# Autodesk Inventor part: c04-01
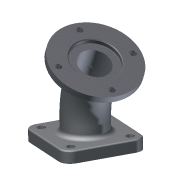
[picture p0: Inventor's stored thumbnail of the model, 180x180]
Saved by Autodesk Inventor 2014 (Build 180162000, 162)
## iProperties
Created: 2010-11
Part Number: c04-01
Material: Generic
Document SubType Name: Modeling
Designer: Thom Tremblay
Density: 1 g/cm^3
Appearance: Aluminum Cast
Author: Thom Tremblay
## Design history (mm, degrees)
sketch "Sketch1"
  geometry: L1 (50, 50)-(50, -50); L2 (50, -50)-(-50, -50); L3 (-50, -50)-(-50, 50); L4 (-50, 50)-(50, 50); C1 r 28 at (0, 0); C2 r 20 at (0, 0); 2 further points
  constraints: 8 end point, 3 coincident, 2 centre point, 1 horizontal, 9 other
  dimensions: "d0" = 100 distance of L3.end L1.start; "d8" = 8 radial gap between concentric circles of C1 C2; "d17" = 40 diameter of C2
extrude "Extrusion1" new body sketch "Sketch1" distance "d1" = 15; taper "d2" = 0 deg
sketch "Sketch2"
  geometry: L1 (0, 0)-(0, 30); L2 (-13.397, 80)-(-28.397, 105.981); A1 r 100 centre (-100, 30) between (0, 30) and (-13.397, 80)
  constraints: 4 end point, 2 point on circle, 2 tangent, 1 centre point, 1 vertical
  dimensions: "d3" = 30 distance of L1.start L1.end; "d4" = 30 distance of L2.start L2.end; "d5" = 150 deg angle of L1 L2; "d6" = 100 radius of A1
workplane "Work Plane1"
sketch "Sketch3"
  geometry: C1 r 55 at (0, 0); 2 further points
  constraints: 1 centre point, 1 coincident
  dimensions: "d9" = 110 diameter of C1
extrude "Extrusion2" join sketch "Sketch3" distance "d10" = 10; taper "d11" = 0 deg
sweep "Sweep1" dims "d12" = 0
sweep "Sweep2" dims "d13" = 0
fillet "Fillet1" dims "d14" = 14, "d15" = 6, "d16" = 2
hole "Hole1" diameter "d20" = 11; stored, may be unused: countersink angle "d24" = 90 deg, drill point angle "d26" = 118 deg; dims "d18" = 10, "d19" = 10, "d21" = 6, "d22" = 20, "d23" = 2, "d25" = 8
hole "Hole2" diameter "d29" = 11; stored, may be unused: countersink angle "d33" = 90 deg, drill point angle "d35" = 118 deg; dims "d27" = 10, "d28" = 10, "d30" = 6, "d31" = 20, "d32" = 2, "d34" = 8
hole "Hole3" diameter "d38" = 11; stored, may be unused: countersink angle "d42" = 90 deg, drill point angle "d44" = 118 deg; dims "d36" = 10, "d37" = 10, "d39" = 6, "d40" = 20, "d41" = 2, "d43" = 8
hole "Hole4" diameter "d47" = 11; stored, may be unused: countersink angle "d51" = 90 deg, drill point angle "d53" = 118 deg; dims "d45" = 10, "d46" = 10, "d48" = 6, "d49" = 20, "d50" = 2, "d52" = 8
sketch "Sketch4" dims "d54" = 90
  geometry: L1 (0, 45)-(45, 0); L2 (45, 0)-(0, -45); L3 (0, -45)-(-45, 0); L4 (-45, 0)-(0, 45); C1 r 55 at (0, 0) reference; 3 further points
  constraints: 8 end point, 2 coincident, 1 vertical alignment, 11 other
hole "Hole5" sketch "Sketch4" at (0, 45), (45, 0), (0, -45), (-45, 0) diameter "d55" = 8.376; stored, may be unused: countersink angle "d59" = 90 deg, drill point angle "d61" = 118 deg; dims "d56" = 6, "d57" = 20, "d58" = 2, "d60" = 8
sketch "Sketch5"
  geometry: C1 r 55 at (0, 0) reference; C2 r 30 at (0, 0); 1 further point
  constraints: 1 centre point, 1 coincident
  dimensions: "d62" = 60 diameter of C2
extrude "Extrusion3" cut sketch "Sketch5" distance "d63" = 6; taper "d64" = 0 deg
sketch "Sketch6"
  geometry: C1 r 20 at (0, 0) reference; C2 r 30 at (0, 0); C3 r 33 at (0, 0)
  constraints: 2 centre point, 1 coincident
  dimensions: "d65" = 60 diameter of C2; "d66" = 3 radial gap between concentric circles of C3 C2
extrude "Extrusion4" cut sketch "Sketch6" distance "d67" = 3; taper "d68" = 0 deg
fillet "Fillet2" dims "d69" = 0.5
chamfer "Chamfer1" distance "d70" = 2; stored, may be unused: second distance "d71" = 2, angle "d72" = 45 deg
chamfer "Chamfer2" distance "d73" = 1; stored, may be unused: second distance "d74" = 2, angle "d75" = 45 deg
fillet "Fillet3" dims "d76" = 0.5
body "Solid1"
